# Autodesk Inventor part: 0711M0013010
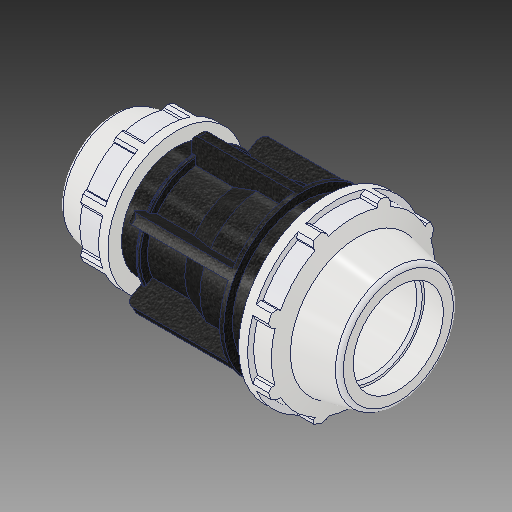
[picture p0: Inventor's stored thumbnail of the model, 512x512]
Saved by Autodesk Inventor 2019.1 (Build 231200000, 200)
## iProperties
Created: 2017-02
Part Number: 0711M0013010
Material: PVC-Piping
Description: PLASSON REDUCING COUPLER 1 1/4'' - 3/4''
Document SubType Name: Modeling
Designer: KIM
Mass: 92.6774 g
Surface Area: 199.44 cm^2
Volume: 66.1981 cm^3
Density: 1.4 g/cm^3
Appearance: PTFE
Author: KIM
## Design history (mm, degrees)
derived "0711M0.ipt"
feature "Solid1::0711M0.ipt"
tag "TaggingFeature1"
body "Solid1"
other parameters: "d_" = 42.1, "E_" = 82.042, "H_" = 133, "l_" = 64.008, "d_1" = 33.3, "E_1" = 64.008, "l_1" = 58, "d96" = 8.1047, "d2" = 42.1, "d4" = 11.08333, "d5" = 19, "d7" = 82.042, "d9" = 19, "d11" = 1.9, "d12" = 65.6336, "d13" = 120 deg, "d14" = 54.73, "d15" = 12 deg, "d16" = 73.8378, "d18" = 2.105, "d19" = 35 deg, "d20" = 17.5 deg, "d21" = 76.29906, "d23" = 0, "d25" = 360 deg, "d27" = 1.64084, "d42" = 14.63, "d46" = 1.263, "d51" = 133, "d52" = 45.86207, "d53" = 12 deg, "d54" = 64.008, "d56" = 49.95, "d57" = 33.3, "d58" = 37.89, "d59" = 29.97, "d60" = 57.6072, "d61" = 51.2064, "d62" = 13.3, "d63" = 15.96, "d64" = 120 deg, "d65" = 64.008, "d68" = 9.5, "d74" = 59.52744, "d75" = 35 deg, "d76" = 17.5 deg, "d78" = 0, "d80" = 360 deg, "d85" = 1.28016, "d88" = 0.666, "d93" = 58, "d94" = 57.4294, "d97" = 2.70157, "d98" = 4.2672, "d99" = 0, "d100" = 3.28168, "d102" = 360 deg, "d104" = 2, "d106" = 0, "d107" = 4.2672, "d108" = 0, "d109" = 4.2672, "d110" = 0
